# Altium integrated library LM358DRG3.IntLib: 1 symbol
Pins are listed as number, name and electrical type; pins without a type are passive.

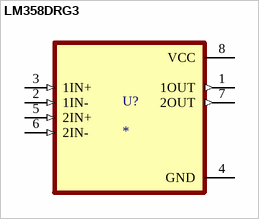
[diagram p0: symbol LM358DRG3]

## LM358DRG3
designator U?
Dual, 30-V, 700-kHz operational amplifier; MF: Texas Instruments; MP: LM358DRG3
footprint SOIC127P599X175-8N
pins: 1 1OUT (out), 2 1IN- (in), 3 1IN+ (in), 4 GND (power), 5 2IN+ (in), 6 2IN- (in), 7 2OUT (out), 8 VCC (power)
